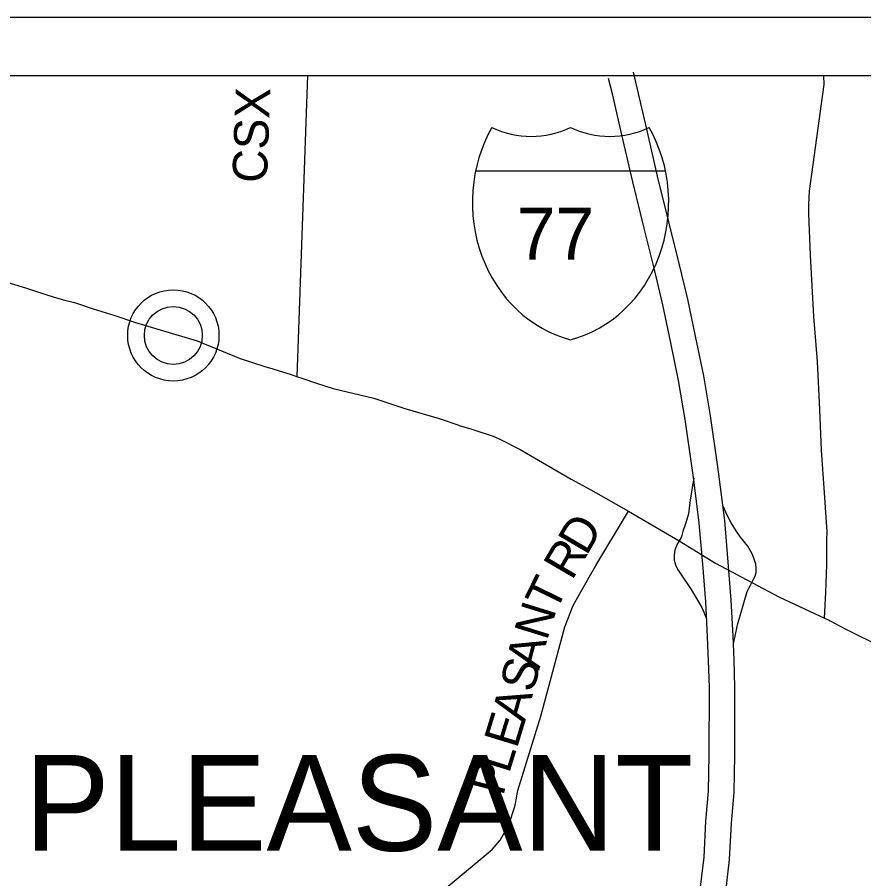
# Model space of a CAD drawing. Extents: x 0 to 34, y 0 to 22.
# Drawn here: x 26.145 to 27.522, y 19.156 to 20.557 of the extents above; entities that cross this region are included whole.
import ezdxf

# ---------------------------------------------------------------- set-up
doc = ezdxf.new("R2010")
doc.units = 0
for name, color, linetype in [('Default', 7, 'Continuous'), ('GM_X_County_Road_Text', 7, 'Continuous'), ('GM_X_Interchange_Ramps', 7, 'Continuous'), ('GM_X_Major_River', 7, 'Continuous'), ('GM_X_State_Route', 7, 'Continuous'), ('GM_X_Unincorporated', 7, 'Continuous'), ('GM_X_Unincorporated_Text', 7, 'Continuous')]:
    doc.layers.add(name, color=color, linetype=linetype)

msp = doc.modelspace()

# ---------------------------------------------------------------- linework, layer by layer
at = {"layer": 'Default'}
msp.add_line((19.8526, 20.4625), (30.697, 20.4625), dxfattribs=at)
msp.add_lwpolyline([(19.7581, 20.557), (30.7915, 20.557), (30.7915, 9.5237), (19.7581, 9.5237)], close=True, dxfattribs=at)
for points in [[(26.6006, 19.9728), (26.6181, 20.4625)], [(27.4584, 19.5799), (27.4602, 19.6216), (27.4621, 19.667), (27.4617, 19.7071), (27.4623, 19.7201), (27.4583, 19.7837), (27.453, 19.8533), (27.4507, 19.919), (27.4467, 19.9971), (27.4408, 20.0702), (27.4354, 20.1699), (27.4325, 20.2376), (27.4327, 20.2533), (27.4336, 20.2744), (27.4578, 20.4475), (27.457, 20.4625)], [(26.9555, 19.2789), (26.9597, 19.2998), (26.997, 19.4208), (27.0356, 19.5658), (27.0496, 19.6008), (27.0597, 19.6192), (27.0864, 19.6657), (27.1392, 19.7542)], [(26.6544, 18.8848), (26.6866, 18.9336), (26.7357, 19.0086), (26.7826, 19.0814), (26.7971, 19.1028), (26.8101, 19.1147), (26.9177, 19.2038), (26.9307, 19.2192), (26.9383, 19.2328), (26.9453, 19.2455), (26.9545, 19.2737), (26.9555, 19.2789)]]:
    msp.add_lwpolyline(points, dxfattribs=at)
for centre, major_axis, start_param, end_param in [((27.0915, 20.2558), (0, -0.2289), 4.15077, 6.05619), ((26.9812, 20.5459), (0, -0.1826), 5.88324, 6.683049), ((26.9988, 20.2558), (0, -0.2289), 0.227007, 2.13242), ((27.1092, 20.546), (0, -0.1827), 5.883359, 6.683012)]:
    msp.add_ellipse(centre, major_axis=major_axis, ratio=0.9, start_param=start_param, end_param=end_param, dxfattribs=at)
at = {"layer": 'GM_X_Interchange_Ramps'}
for points in [[(27.2454, 19.8075), (27.2429, 19.7926), (27.2396, 19.7716), (27.2369, 19.7497), (27.2327, 19.7351), (27.2303, 19.7285), (27.2282, 19.7228), (27.2256, 19.712), (27.2216, 19.7055)], [(27.34, 19.6379), (27.3426, 19.6435), (27.3454, 19.6482), (27.3469, 19.6543), (27.3471, 19.6617), (27.3464, 19.668), (27.344, 19.6761), (27.3403, 19.6848), (27.3332, 19.6968), (27.3217, 19.7117), (27.3145, 19.7222), (27.3061, 19.7348), (27.3002, 19.7464), (27.2928, 19.7634)], [(27.2216, 19.7055), (27.2185, 19.7002), (27.2148, 19.6906), (27.2136, 19.6825), (27.2139, 19.6743), (27.2159, 19.6665), (27.219, 19.6597), (27.2234, 19.653), (27.2412, 19.6264), (27.2468, 19.6173), (27.2589, 19.5975), (27.2665, 19.5797)], [(27.3101, 19.539), (27.3126, 19.5505), (27.3166, 19.5691), (27.3323, 19.6234), (27.335, 19.6287), (27.3375, 19.6323), (27.34, 19.6379)]]:
    msp.add_lwpolyline(points, dxfattribs=at)
at = {"layer": 'GM_X_Major_River'}
msp.add_line((26.8913, 20.3073), (27.1995, 20.3073), dxfattribs=at)
at = {"layer": 'GM_X_State_Route'}
for points in [[(27.3017, 19.6712), (27.2958, 19.7388), (27.2891, 19.793), (27.2862, 19.8143), (27.2842, 19.8296), (27.2728, 19.9092), (27.2617, 19.9741), (27.2484, 20.0387), (27.2359, 20.0987), (27.2214, 20.1588), (27.2051, 20.2242), (27.1868, 20.2988), (27.1692, 20.375), (27.1536, 20.4424), (27.1475, 20.4675)], [(27.2603, 19.6676), (27.2545, 19.7344), (27.2479, 19.7877), (27.245, 19.8088), (27.243, 19.8239), (27.2318, 19.9028), (27.2209, 19.9664), (27.2077, 20.0303), (27.1953, 20.0896), (27.181, 20.1489), (27.1647, 20.2142), (27.1463, 20.2892), (27.1287, 20.3656), (27.1132, 20.4327), (27.1071, 20.4575)], [(26.1116, 20.131), (26.1587, 20.117), (26.1735, 20.1123), (26.2055, 20.1018), (26.2229, 20.0971), (26.2383, 20.093), (26.2686, 20.0831), (26.304, 20.0721), (26.3379, 20.0605), (26.438, 20.0307), (26.508, 20.0021), (26.5232, 19.9972), (26.5497, 19.9886), (26.5557, 19.9868), (26.5892, 19.9766), (26.601, 19.9726), (26.608, 19.9703), (26.6318, 19.9623), (26.6589, 19.9536), (26.7253, 19.9377), (26.7495, 19.9297)], [(26.7495, 19.9297), (26.7755, 19.921), (26.8316, 19.9047), (26.8637, 19.8935)], [(26.8637, 19.8935), (26.864, 19.8934), (26.8844, 19.8874), (26.9192, 19.8758), (26.9315, 19.8707), (26.9632, 19.8541), (27.0463, 19.8062), (27.0782, 19.7884)], [(27.0782, 19.7884), (27.1392, 19.7542), (27.2216, 19.7055), (27.281, 19.6694), (27.34, 19.6379), (27.3849, 19.6142)], [(27.0918, 18.2475), (27.1066, 18.3161), (27.1233, 18.4012), (27.1397, 18.4872), (27.1554, 18.5608), (27.1689, 18.6316), (27.1839, 18.7062), (27.1996, 18.7817), (27.2156, 18.8624), (27.2287, 18.9312), (27.2399, 18.9951), (27.249, 19.067), (27.2551, 19.1298), (27.2622, 19.1912), (27.2652, 19.2497), (27.2696, 19.2987), (27.2708, 19.3576), (27.2709, 19.4673), (27.2695, 19.511), (27.2681, 19.5495), (27.2651, 19.6066), (27.2603, 19.6678)], [(27.1325, 18.2387), (27.1474, 18.3077), (27.1641, 18.3933), (27.1805, 18.4789), (27.1962, 18.5526), (27.2097, 18.6237), (27.2247, 18.6979), (27.2404, 18.7734), (27.2565, 18.8544), (27.2696, 18.9237), (27.2811, 18.9889), (27.2904, 19.0624), (27.2965, 19.1254), (27.3036, 19.1877), (27.3067, 19.2467), (27.3112, 19.2964), (27.3124, 19.3572), (27.3125, 19.4679), (27.3111, 19.5124), (27.3096, 19.5514), (27.3066, 19.6093), (27.3017, 19.671)], [(27.3849, 19.6142), (27.3849, 19.6142), (27.4584, 19.5799), (27.4655, 19.5766), (27.4673, 19.5756)], [(27.4673, 19.5756), (27.4916, 19.5625), (27.5167, 19.5504), (27.5272, 19.5453), (27.5686, 19.5252), (27.5962, 19.5118), (27.6423, 19.4879), (27.6534, 19.4834)]]:
    msp.add_lwpolyline(points, dxfattribs=at)
at = {"layer": 'GM_X_Unincorporated'}
for radius in [0.0742, 0.0471]:
    msp.add_circle((26.3992, 20.0397), radius, dxfattribs=at)

# ---------------------------------------------------------------- texts
at = {"layer": 'Default'}
msp.add_text('CSX', height=0.05635, rotation=87.878, dxfattribs=at).set_placement((26.5513, 20.2868))
msp.add_text('77', height=0.08462, dxfattribs=at).set_placement((26.9577, 20.163))
at = {"layer": 'GM_X_County_Road_Text'}
for s, rotation, p in [('D', 59.567, (27.0709, 19.6801)), ('R', 59.6263, (27.0474, 19.6399)), ('T', 64.0416, (27.0207, 19.5876)), ('N', 72.728, (27.0067, 19.5421)), ('A', 75.2028, (26.9941, 19.4945)), ('S', 75.1804, (26.9843, 19.4575)), ('A', 74.2274, (26.9705, 19.4085)), ('E', 72.9379, (26.9577, 19.3666)), ('L', 72.856, (26.9451, 19.326)), ('P', 75.3489, (26.9356, 19.2896))]:
    msp.add_text(s, height=0.0567, rotation=rotation, dxfattribs=at).set_placement(p)
at = {"layer": 'GM_X_Unincorporated_Text'}
msp.add_text('PLEASANT', height=0.15568, rotation=0, dxfattribs=at).set_placement((26.1572, 19.2018))

doc.saveas('drawing.dxf')
